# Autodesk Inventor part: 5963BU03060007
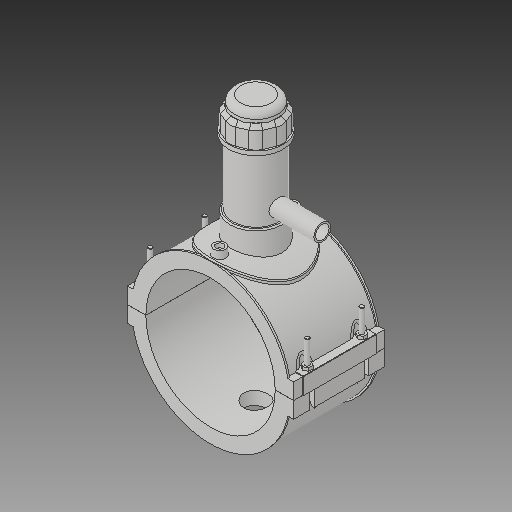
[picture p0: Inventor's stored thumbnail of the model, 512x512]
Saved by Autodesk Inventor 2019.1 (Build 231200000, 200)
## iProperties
Created: 2017-07
Part Number: 5963BU03060007
Material: Generic
Description: PLASSON TAPPING SADDLE 6''IPS x 1 3/4''CTS
Document SubType Name: Modeling
Designer: KIM
Mass: 1712.7 g
Surface Area: 2671.49 cm^2
Volume: 1712.7 cm^3
Density: 1 g/cm^3
Appearance: Default
Author: KIM
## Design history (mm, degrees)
derived "5963B.ipt"
feature "Solid1::5963B.ipt"
feature "Solid2::5963B.ipt"
feature "Solid4::5963B.ipt"
feature "Solid5::5963B.ipt"
tag "TaggingFeature1"
body "Solid1"
body "Solid2"
other parameters: "d0" = 168, "d2" = 215.9, "d3" = 42, "d4" = 118.11, "d5" = 0, "d6" = 0.1, "d8" = 0, "d19" = 6, "d20" = 6, "d21" = 70.866, "d23" = 0, "d24" = 35.433, "d26" = 0, "d29" = 3, "d30" = 56, "d31" = 6, "d32" = 0, "d33" = 0, "d34" = 0.6, "d40" = 104.832, "d41" = 117.6, "d43" = 0, "d45" = 0, "d47" = 171.666, "d70" = 15, "d72" = 0, "d73" = 6, "d75" = 5, "d76" = 0, "d77" = 8.4, "d78" = 114, "d79" = 15, "d80" = 47.244, "d82" = 5 deg, "d84" = 4, "d85" = 14, "d86" = 0, "d87" = 3, "d88" = 0, "d89" = 1, "d90" = 1, "d91" = 94.488, "d92" = 0, "d93" = 0.5, "d94" = 88.42105, "d96" = 205.632, "d97" = 2.3622, "d98" = 0, "d102" = 1.68, "d120" = 140 deg, "d121" = 24.228, "d122" = 20 deg, "d123" = 403.2, "d124" = 120.96, "d126" = 0, "d143" = 173.04, "d145" = 25.84615, "d149" = 2.52, "d150" = 28.43077, "d153" = 118.11, "d154" = 0, "d156" = 100.8, "d157" = 160 deg, "d159" = 6.72, "d161" = 2.52, "d162" = 70.866, "d163" = 0, "d164" = 84, "d167" = 16.8, "d168" = 98.34146, "d170" = 3.2805, "d172" = 0, "d173" = 1, "d175" = 84, "d176" = 20 deg, "d177" = 11.76, "d178" = 33.6, "d180" = 0, "d183" = 13.44, "d184" = 9.408, "d185" = 38.38575, "d186" = 38.38575, "d187" = 100.8, "d188" = 10.08, "d189" = 11.76, "d190" = 0, "d191" = 151.2, "d193" = 6.1236, "d194" = 4.13385, "d195" = 90 deg, "d197" = 0, "d199" = 0, "d200" = 16.8, "d202" = 0, "d203" = 177.038, "d204" = 67.032, "d205" = 49.392, "d206" = 59.976, "d207" = 132.7785, "d208" = 138.08964, "d209" = 164.64534, "d210" = 60.6816, "d211" = 70.56, "d212" = 56.448, "d213" = 48.5766, "d216" = 0, "d217" = 16.8, "d218" = 8.4, "d219" = 1.68, "d222" = 168, "d224" = 0, "d230" = 5.04, "d233" = 6, "d236" = 107.95, "d237" = 35.433, "d238" = 6.02433, "d240" = 35.433, "d241" = 35.433, "d242" = 35.433, "d243" = 6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
